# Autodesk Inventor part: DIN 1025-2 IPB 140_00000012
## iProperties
Created: 2006-02
Part Number: DIN 1025-2 IPB 140_00000012
Material: Default
Document SubType Name: Modeling
Designer: 40664
Manufacturer: Standard
Standards Organization: Custom
Stock Number: DIN 1025-2 IPB 140
Mass: 11082.6 g
Surface Area: 20865.2 cm^2
Volume: 11082.6 cm^3
Density: 1 g/cm^3
G_L: 2580.000 mm
G_W: 140.000 mm
G_H: 140.000 mm
AFG_Item: IPB 140
CSToolsMass: 11.0
CSToolsVolume: 11082628.0
CSToolsArea: 20865.0
Author: 40664
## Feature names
1. AFG_Detailed_DIN 1025-2 IPB 140_00000012 [Extrusion]
2. AFG_Simplified_DIN 1025-2 IPB 140_00000012 [Extrusion]
